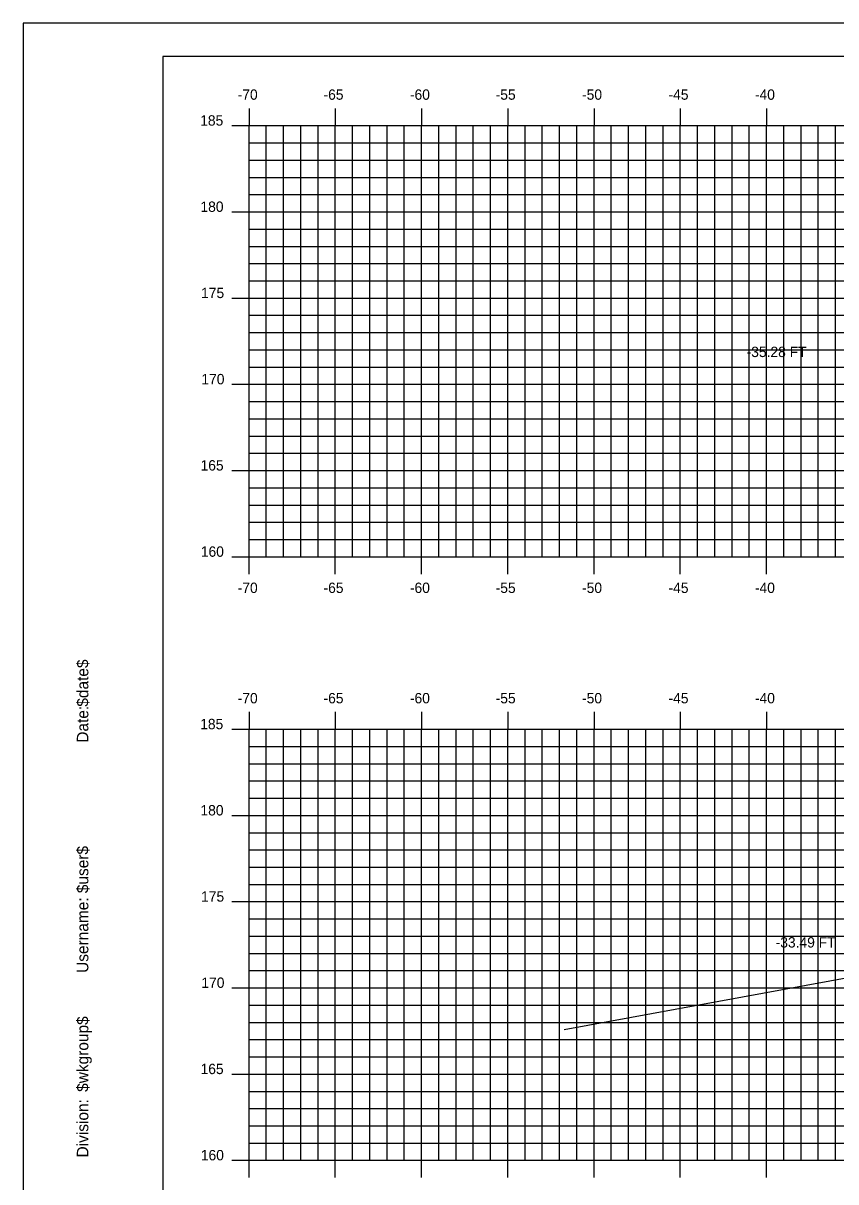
# Model space of a CAD drawing. Extents: x 1140537 to 1140707, y 608981 to 609091.
# Drawn here: x 1140537.2 to 1140584.3, y 609024.1 to 609091.3 of the extents above; entities that cross this region are included whole.
import ezdxf

# ---------------------------------------------------------------- set-up
doc = ezdxf.new("R2010")
doc.units = 0
for name, color, linetype in [('BORDER', 7, 'Continuous'), ('D_Text_Standard', 7, 'Continuous'), ('H_V ANNOTATION', 7, 'Continuous'), ('MAJOR', 7, 'Continuous'), ('MINOR', 7, 'Continuous'), ('PLOT BOUNDARY', 7, 'Continuous'), ('S_Roadway_Centerline', 7, 'Continuous')]:
    doc.layers.add(name, color=color, linetype=linetype)

msp = doc.modelspace()

# ---------------------------------------------------------------- linework, layer by layer
at = {"layer": 'BORDER'}
msp.add_lwpolyline([(1140545.245, 608984.335), (1140705.245, 608984.335), (1140705.245, 609089.335), (1140545.245, 609089.335)], close=True, dxfattribs=at)
at = {"layer": 'MAJOR'}
for p, q in [((1140550.245, 609086.337), (1140550.245, 609085.335)), ((1140555.245, 609086.337), (1140555.245, 609085.335)), ((1140560.245, 609086.337), (1140560.245, 609085.335)), ((1140565.245, 609086.337), (1140565.245, 609085.335)), ((1140570.245, 609086.337), (1140570.245, 609085.335)), ((1140575.245, 609086.337), (1140575.245, 609085.335)), ((1140580.245, 609086.337), (1140580.245, 609085.335)), ((1140549.243, 609085.335), (1140550.245, 609085.335)), ((1140550.245, 609085.335), (1140690.245, 609085.335)), ((1140550.245, 609060.335), (1140550.245, 609085.335)), ((1140550.245, 609060.335), (1140550.245, 609085.335)), ((1140550.245, 609085.335), (1140690.245, 609085.335)), ((1140555.245, 609060.335), (1140555.245, 609085.335)), ((1140560.245, 609060.335), (1140560.245, 609085.335)), ((1140565.245, 609060.335), (1140565.245, 609085.335)), ((1140570.245, 609060.335), (1140570.245, 609085.335)), ((1140575.245, 609060.335), (1140575.245, 609085.335)), ((1140580.245, 609060.335), (1140580.245, 609085.335)), ((1140549.243, 609080.335), (1140550.245, 609080.335)), ((1140550.245, 609080.335), (1140690.245, 609080.335)), ((1140549.243, 609075.335), (1140550.245, 609075.335)), ((1140550.245, 609075.335), (1140690.245, 609075.335)), ((1140549.243, 609070.335), (1140550.245, 609070.335)), ((1140550.245, 609070.335), (1140690.245, 609070.335)), ((1140549.243, 609065.335), (1140550.245, 609065.335)), ((1140550.245, 609065.335), (1140690.245, 609065.335)), ((1140549.243, 609060.335), (1140550.245, 609060.335)), ((1140550.245, 609060.335), (1140690.245, 609060.335)), ((1140550.245, 609060.335), (1140690.245, 609060.335)), ((1140550.245, 609059.333), (1140550.245, 609060.335)), ((1140555.245, 609059.333), (1140555.245, 609060.335)), ((1140560.245, 609059.333), (1140560.245, 609060.335)), ((1140565.245, 609059.333), (1140565.245, 609060.335)), ((1140570.245, 609059.333), (1140570.245, 609060.335)), ((1140575.245, 609059.333), (1140575.245, 609060.335)), ((1140580.245, 609059.333), (1140580.245, 609060.335)), ((1140550.245, 609051.337), (1140550.245, 609050.335)), ((1140555.245, 609051.337), (1140555.245, 609050.335)), ((1140560.245, 609051.337), (1140560.245, 609050.335)), ((1140565.245, 609051.337), (1140565.245, 609050.335)), ((1140570.245, 609051.337), (1140570.245, 609050.335)), ((1140575.245, 609051.337), (1140575.245, 609050.335)), ((1140580.245, 609051.337), (1140580.245, 609050.335)), ((1140549.243, 609050.335), (1140550.245, 609050.335)), ((1140550.245, 609050.335), (1140690.245, 609050.335)), ((1140550.245, 609025.335), (1140550.245, 609050.335)), ((1140550.245, 609025.335), (1140550.245, 609050.335)), ((1140550.245, 609050.335), (1140690.245, 609050.335)), ((1140555.245, 609025.335), (1140555.245, 609050.335)), ((1140560.245, 609025.335), (1140560.245, 609050.335)), ((1140565.245, 609025.335), (1140565.245, 609050.335)), ((1140570.245, 609025.335), (1140570.245, 609050.335)), ((1140575.245, 609025.335), (1140575.245, 609050.335)), ((1140580.245, 609025.335), (1140580.245, 609050.335)), ((1140549.243, 609045.335), (1140550.245, 609045.335)), ((1140550.245, 609045.335), (1140690.245, 609045.335)), ((1140549.243, 609040.335), (1140550.245, 609040.335)), ((1140550.245, 609040.335), (1140690.245, 609040.335)), ((1140549.243, 609035.335), (1140550.245, 609035.335)), ((1140550.245, 609035.335), (1140690.245, 609035.335)), ((1140549.243, 609030.335), (1140550.245, 609030.335)), ((1140550.245, 609030.335), (1140690.245, 609030.335)), ((1140549.243, 609025.335), (1140550.245, 609025.335)), ((1140550.245, 609025.335), (1140690.245, 609025.335)), ((1140550.245, 609025.335), (1140690.245, 609025.335)), ((1140550.245, 609024.333), (1140550.245, 609025.335)), ((1140555.245, 609024.333), (1140555.245, 609025.335)), ((1140560.245, 609024.333), (1140560.245, 609025.335)), ((1140565.245, 609024.333), (1140565.245, 609025.335)), ((1140570.245, 609024.333), (1140570.245, 609025.335)), ((1140575.245, 609024.333), (1140575.245, 609025.335)), ((1140580.245, 609024.333), (1140580.245, 609025.335))]:
    msp.add_line(p, q, dxfattribs=at)
at = {"layer": 'MINOR'}
for p, q in [((1140551.245, 609060.335), (1140551.245, 609085.335)), ((1140552.245, 609060.335), (1140552.245, 609085.335)), ((1140553.245, 609060.335), (1140553.245, 609085.335)), ((1140554.245, 609060.335), (1140554.245, 609085.335)), ((1140556.245, 609060.335), (1140556.245, 609085.335)), ((1140557.245, 609060.335), (1140557.245, 609085.335)), ((1140558.245, 609060.335), (1140558.245, 609085.335)), ((1140559.245, 609060.335), (1140559.245, 609085.335)), ((1140561.245, 609060.335), (1140561.245, 609085.335)), ((1140562.245, 609060.335), (1140562.245, 609085.335)), ((1140563.245, 609060.335), (1140563.245, 609085.335)), ((1140564.245, 609060.335), (1140564.245, 609085.335)), ((1140566.245, 609060.335), (1140566.245, 609085.335)), ((1140567.245, 609060.335), (1140567.245, 609085.335)), ((1140568.245, 609060.335), (1140568.245, 609085.335)), ((1140569.245, 609060.335), (1140569.245, 609085.335)), ((1140571.245, 609060.335), (1140571.245, 609085.335)), ((1140572.245, 609060.335), (1140572.245, 609085.335)), ((1140573.245, 609060.335), (1140573.245, 609085.335)), ((1140574.245, 609060.335), (1140574.245, 609085.335)), ((1140576.245, 609060.335), (1140576.245, 609085.335)), ((1140577.245, 609060.335), (1140577.245, 609085.335)), ((1140578.245, 609060.335), (1140578.245, 609085.335)), ((1140579.245, 609060.335), (1140579.245, 609085.335)), ((1140581.245, 609060.335), (1140581.245, 609085.335)), ((1140582.245, 609060.335), (1140582.245, 609085.335)), ((1140583.245, 609060.335), (1140583.245, 609085.335)), ((1140584.245, 609060.335), (1140584.245, 609085.335)), ((1140550.245, 609084.335), (1140690.245, 609084.335)), ((1140550.245, 609084.335), (1140551.247, 609084.335)), ((1140550.245, 609083.335), (1140690.245, 609083.335)), ((1140550.245, 609083.335), (1140551.247, 609083.335)), ((1140550.245, 609082.335), (1140690.245, 609082.335)), ((1140550.245, 609082.335), (1140551.247, 609082.335)), ((1140550.245, 609081.335), (1140690.245, 609081.335)), ((1140550.245, 609081.335), (1140551.247, 609081.335)), ((1140550.245, 609079.335), (1140690.245, 609079.335)), ((1140550.245, 609079.335), (1140551.247, 609079.335)), ((1140550.245, 609078.335), (1140690.245, 609078.335)), ((1140550.245, 609078.335), (1140551.247, 609078.335)), ((1140550.245, 609077.335), (1140690.245, 609077.335)), ((1140550.245, 609077.335), (1140551.247, 609077.335)), ((1140550.245, 609076.335), (1140690.245, 609076.335)), ((1140550.245, 609076.335), (1140551.247, 609076.335)), ((1140550.245, 609074.335), (1140690.245, 609074.335)), ((1140550.245, 609074.335), (1140551.247, 609074.335)), ((1140550.245, 609073.335), (1140690.245, 609073.335)), ((1140550.245, 609073.335), (1140551.247, 609073.335)), ((1140550.245, 609072.335), (1140690.245, 609072.335)), ((1140550.245, 609072.335), (1140551.247, 609072.335)), ((1140550.245, 609071.335), (1140690.245, 609071.335)), ((1140550.245, 609071.335), (1140551.247, 609071.335)), ((1140550.245, 609069.335), (1140690.245, 609069.335)), ((1140550.245, 609069.335), (1140551.247, 609069.335)), ((1140550.245, 609068.335), (1140690.245, 609068.335)), ((1140550.245, 609068.335), (1140551.247, 609068.335)), ((1140550.245, 609067.335), (1140690.245, 609067.335)), ((1140550.245, 609067.335), (1140551.247, 609067.335)), ((1140550.245, 609066.335), (1140690.245, 609066.335)), ((1140550.245, 609066.335), (1140551.247, 609066.335)), ((1140550.245, 609064.335), (1140690.245, 609064.335)), ((1140550.245, 609064.335), (1140551.247, 609064.335)), ((1140550.245, 609063.335), (1140690.245, 609063.335)), ((1140550.245, 609063.335), (1140551.247, 609063.335)), ((1140550.245, 609062.335), (1140690.245, 609062.335)), ((1140550.245, 609062.335), (1140551.247, 609062.335)), ((1140550.245, 609061.335), (1140690.245, 609061.335)), ((1140550.245, 609061.335), (1140551.247, 609061.335)), ((1140551.245, 609025.335), (1140551.245, 609050.335)), ((1140552.245, 609025.335), (1140552.245, 609050.335)), ((1140553.245, 609025.335), (1140553.245, 609050.335)), ((1140554.245, 609025.335), (1140554.245, 609050.335)), ((1140556.245, 609025.335), (1140556.245, 609050.335)), ((1140557.245, 609025.335), (1140557.245, 609050.335)), ((1140558.245, 609025.335), (1140558.245, 609050.335)), ((1140559.245, 609025.335), (1140559.245, 609050.335)), ((1140561.245, 609025.335), (1140561.245, 609050.335)), ((1140562.245, 609025.335), (1140562.245, 609050.335)), ((1140563.245, 609025.335), (1140563.245, 609050.335)), ((1140564.245, 609025.335), (1140564.245, 609050.335)), ((1140566.245, 609025.335), (1140566.245, 609050.335)), ((1140567.245, 609025.335), (1140567.245, 609050.335)), ((1140568.245, 609025.335), (1140568.245, 609050.335)), ((1140569.245, 609025.335), (1140569.245, 609050.335)), ((1140571.245, 609025.335), (1140571.245, 609050.335)), ((1140572.245, 609025.335), (1140572.245, 609050.335)), ((1140573.245, 609025.335), (1140573.245, 609050.335)), ((1140574.245, 609025.335), (1140574.245, 609050.335)), ((1140576.245, 609025.335), (1140576.245, 609050.335)), ((1140577.245, 609025.335), (1140577.245, 609050.335)), ((1140578.245, 609025.335), (1140578.245, 609050.335)), ((1140579.245, 609025.335), (1140579.245, 609050.335)), ((1140581.245, 609025.335), (1140581.245, 609050.335)), ((1140582.245, 609025.335), (1140582.245, 609050.335)), ((1140583.245, 609025.335), (1140583.245, 609050.335)), ((1140584.245, 609025.335), (1140584.245, 609050.335)), ((1140550.245, 609049.335), (1140690.245, 609049.335)), ((1140550.245, 609049.335), (1140551.247, 609049.335)), ((1140550.245, 609048.335), (1140690.245, 609048.335)), ((1140550.245, 609048.335), (1140551.247, 609048.335)), ((1140550.245, 609047.335), (1140690.245, 609047.335)), ((1140550.245, 609047.335), (1140551.247, 609047.335)), ((1140550.245, 609046.335), (1140690.245, 609046.335)), ((1140550.245, 609046.335), (1140551.247, 609046.335)), ((1140550.245, 609044.335), (1140690.245, 609044.335)), ((1140550.245, 609044.335), (1140551.247, 609044.335)), ((1140550.245, 609043.335), (1140690.245, 609043.335)), ((1140550.245, 609043.335), (1140551.247, 609043.335)), ((1140550.245, 609042.335), (1140690.245, 609042.335)), ((1140550.245, 609042.335), (1140551.247, 609042.335)), ((1140550.245, 609041.335), (1140690.245, 609041.335)), ((1140550.245, 609041.335), (1140551.247, 609041.335)), ((1140550.245, 609039.335), (1140690.245, 609039.335)), ((1140550.245, 609039.335), (1140551.247, 609039.335)), ((1140550.245, 609038.335), (1140690.245, 609038.335)), ((1140550.245, 609038.335), (1140551.247, 609038.335)), ((1140550.245, 609037.335), (1140690.245, 609037.335)), ((1140550.245, 609037.335), (1140551.247, 609037.335)), ((1140550.245, 609036.335), (1140690.245, 609036.335)), ((1140550.245, 609036.335), (1140551.247, 609036.335)), ((1140550.245, 609034.335), (1140690.245, 609034.335)), ((1140550.245, 609034.335), (1140551.247, 609034.335)), ((1140550.245, 609033.335), (1140690.245, 609033.335)), ((1140550.245, 609033.335), (1140551.247, 609033.335)), ((1140550.245, 609032.335), (1140690.245, 609032.335)), ((1140550.245, 609032.335), (1140551.247, 609032.335)), ((1140550.245, 609031.335), (1140690.245, 609031.335)), ((1140550.245, 609031.335), (1140551.247, 609031.335)), ((1140550.245, 609029.335), (1140690.245, 609029.335)), ((1140550.245, 609029.335), (1140551.247, 609029.335)), ((1140550.245, 609028.335), (1140690.245, 609028.335)), ((1140550.245, 609028.335), (1140551.247, 609028.335)), ((1140550.245, 609027.335), (1140690.245, 609027.335)), ((1140550.245, 609027.335), (1140551.247, 609027.335)), ((1140550.245, 609026.335), (1140690.245, 609026.335)), ((1140550.245, 609026.335), (1140551.247, 609026.335))]:
    msp.add_line(p, q, dxfattribs=at)
at = {"layer": 'PLOT BOUNDARY'}
msp.add_lwpolyline([(1140537.151, 608981.276), (1140707.151, 608981.276), (1140707.151, 609091.276), (1140537.151, 609091.276)], close=True, dxfattribs=at)
at = {"layer": 'S_Roadway_Centerline'}
msp.add_lwpolyline([(1140568.516, 609032.928), (1140586.442, 609036.203), (1140589.364, 609036.683), (1140595.12, 609037.457), (1140595.232, 609037.472), (1140597.724, 609037.95), (1140598.011, 609037.721), (1140599.664, 609037.945), (1140602.639, 609038.97), (1140605.355, 609039.978), (1140606.119, 609039.883), (1140607.708, 609040.341), (1140608.295, 609040.438), (1140613.728, 609040.772), (1140618.974, 609040.9), (1140624.409, 609040.769), (1140630.227, 609040.641), (1140633.873, 609040.427), (1140634.56, 609040.361), (1140635.028, 609040.273), (1140638.111, 609039.824)], dxfattribs=at)

# ---------------------------------------------------------------- texts
at = {"layer": 'BORDER'}
for s, p in [('$date$', (1140540.93, 609051.64)), ('Date:', (1140540.93, 609049.552)), ('$user$', (1140540.93, 609040.827)), ('Username:', (1140540.93, 609036.203)), ('$wkgroup$', (1140540.93, 609029.305)), ('Division:', (1140540.93, 609025.501))]:
    msp.add_text(s, height=0.6696, rotation=90, dxfattribs=at).set_placement(p)
at = {"layer": 'D_Text_Standard'}
for s, p in [('-35.28 FT', (1140579.089, 609071.915)), ('-33.49 FT', (1140580.771, 609037.675))]:
    msp.add_text(s, height=0.6, dxfattribs=at).set_placement(p)
at = {"layer": 'H_V ANNOTATION'}
for s, p in [('-70', (1140549.586, 609086.835)), ('-65', (1140554.562, 609086.835)), ('-60', (1140559.57, 609086.835)), ('-55', (1140564.541, 609086.835)), ('-50', (1140569.549, 609086.835)), ('-45', (1140574.562, 609086.835)), ('-40', (1140579.57, 609086.835)), ('185', (1140547.412, 609085.335)), ('180', (1140547.428, 609080.335)), ('175', (1140547.465, 609075.335)), ('170', (1140547.481, 609070.335)), ('165', (1140547.433, 609065.335)), ('160', (1140547.449, 609060.335)), ('-70', (1140549.586, 609058.235)), ('-65', (1140554.562, 609058.235)), ('-60', (1140559.57, 609058.235)), ('-55', (1140564.541, 609058.235)), ('-50', (1140569.549, 609058.235)), ('-45', (1140574.562, 609058.235)), ('-40', (1140579.57, 609058.235)), ('-70', (1140549.586, 609051.835)), ('-65', (1140554.562, 609051.835)), ('-60', (1140559.57, 609051.835)), ('-55', (1140564.541, 609051.835)), ('-50', (1140569.549, 609051.835)), ('-45', (1140574.562, 609051.835)), ('-40', (1140579.57, 609051.835)), ('185', (1140547.412, 609050.335)), ('180', (1140547.428, 609045.335)), ('175', (1140547.465, 609040.335)), ('170', (1140547.481, 609035.335)), ('165', (1140547.433, 609030.335)), ('160', (1140547.449, 609025.335))]:
    msp.add_text(s, height=0.6, dxfattribs=at).set_placement(p)
at = {"layer": 'MAJOR'}
for p in [(1140550.24, 609060.335), (1140550.24, 609025.335)]:
    msp.add_text('-', height=0.006, dxfattribs=at).set_placement(p)

doc.saveas('drawing.dxf')
